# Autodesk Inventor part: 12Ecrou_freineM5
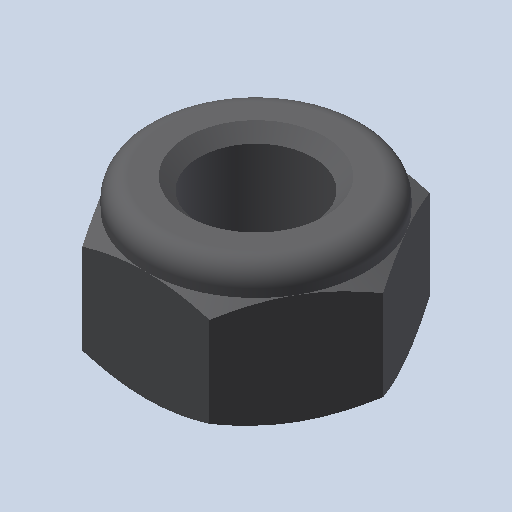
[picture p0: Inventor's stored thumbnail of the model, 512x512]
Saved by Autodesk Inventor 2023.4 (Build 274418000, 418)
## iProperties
Created: 2011-01
Part Number: 12Ecrou_freineM5
Document SubType Name: Modeling
Designer: eric
Density: 1 g/cm^3
Mass: 0.198535 g
Surface Area: 2.65723 cm^2
Volume: 0.198535 cm^3
Material: Générique
Appearance: Yellow
Author: eric
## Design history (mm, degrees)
feature "Base1"
node "Corps solides"
node "Corps surfaciques"
node "Solide1"
